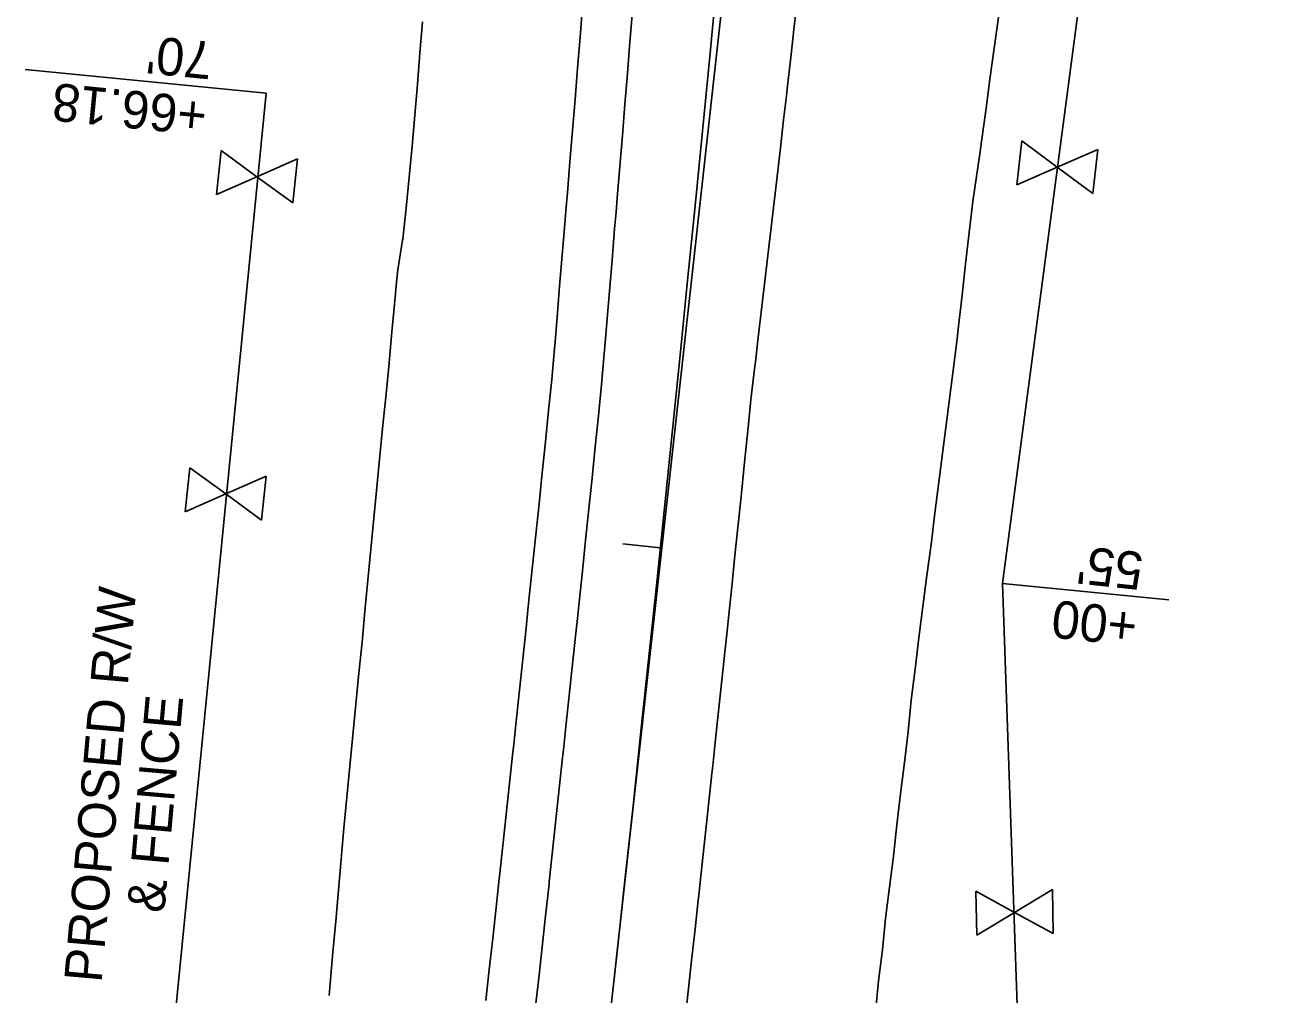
# Model space of a CAD drawing. Extents: x 634057 to 641016, y 287858 to 292331.
# Drawn here: x 634163.1 to 634363.2, y 289595.2 to 289750.2 of the extents above; entities that cross this region are included whole.
import ezdxf

# ---------------------------------------------------------------- set-up
doc = ezdxf.new("R2010")
doc.units = 0
for name, color, linetype in [('53', 7, 'Continuous'), ('R_50 Horz Alg PC PI PT', 7, 'Continuous'), ('R_50 Horz Alg Ticks', 7, 'Continuous'), ('R_Horz Alg', 7, 'Continuous'), ('R_No Plot', 7, 'Continuous'), ('R_Proposed Const Limits', 7, 'Continuous'), ('R_Proposed Road', 7, 'Continuous'), ('R_Proposed Shoulder', 7, 'Continuous'), ('R_ROW', 7, 'Continuous')]:
    doc.layers.add(name, color=color, linetype=linetype)

msp = doc.modelspace()

# ---------------------------------------------------------------- linework, layer by layer
at = {"layer": '53'}
for p, q in [((634201.66, 289739.35), (634163.14, 289743.13)), ((634345.98, 289658.38), (634319.38, 289660.99))]:
    msp.add_line(p, q, dxfattribs=at)
at = {"layer": 'R_50 Horz Alg PC PI PT'}
msp.add_lwpolyline([(634256.46, 289590.15), (634341.05, 290353.77)], dxfattribs=at)
at = {"layer": 'R_50 Horz Alg Ticks'}
msp.add_lwpolyline([(634258.7, 289667.3), (634264.67, 289666.68)], dxfattribs=at)
at = {"layer": 'R_Horz Alg'}
msp.add_arc((622866.97, 290851.82), 11459.16, 353.678846, 1.350269, dxfattribs=at)
at = {"layer": 'R_Proposed Const Limits'}
for points in [[(634318.77, 289751.89), (634318.1, 289746.91), (634317.42, 289741.94), (634316.75, 289736.96), (634316.07, 289731.98), (634315.75, 289729.64)], [(634223.48, 289715.85), (634223.5, 289716.02), (634224.04, 289720.97), (634224.54, 289725.92), (634224.99, 289730.88), (634225.44, 289735.84), (634225.89, 289740.8), (634226.26, 289745.77), (634226.65, 289750.74)], [(634315.75, 289729.64), (634314.64, 289722.04), (634314.06, 289717.05), (634313.48, 289712.06), (634312.9, 289707.08), (634312.35, 289702.09), (634312.14, 289700.13), (634311.75, 289697.1), (634311.1, 289692.12), (634310.47, 289687.15), (634310.47, 289687.14), (634309.85, 289682.16), (634309.2, 289677.18), (634308.56, 289672.2), (634307.95, 289667.22), (634307.29, 289662.24), (634306.64, 289657.27), (634306.02, 289652.28), (634305.4, 289647.3), (634304.77, 289642.32), (634304.27, 289637.33), (634303.7, 289632.34), (634303.06, 289627.37), (634302.49, 289622.38), (634301.96, 289617.39), (634301.32, 289612.41), (634300.67, 289607.43), (634300.19, 289602.44), (634299.53, 289597.46), (634299.05, 289592.46)], [(634211.74, 289595.11), (634211.92, 289597.05), (634212.35, 289602.02), (634212.79, 289606.98), (634213.24, 289611.94), (634213.66, 289616.9), (634214.12, 289621.86), (634214.57, 289626.82), (634215.04, 289631.78), (634215.53, 289636.74), (634216.02, 289641.69), (634216.51, 289646.65), (634217, 289651.61), (634217.47, 289656.56), (634217.94, 289661.52), (634218.43, 289666.48), (634218.91, 289671.43), (634219.39, 289676.39), (634219.86, 289681.35), (634220.35, 289686.3), (634220.85, 289691.26), (634221.35, 289696.21), (634221.35, 289696.22), (634221.77, 289701.18), (634222.24, 289706.13), (634222.53, 289709.15), (634222.72, 289711.09), (634223.48, 289715.85)]]:
    msp.add_lwpolyline(points, dxfattribs=at)
at = {"layer": 'R_Proposed Road'}
for points in [[(634268.6, 289590.78), (634269.15, 289595.76), (634269.69, 289600.73), (634270.24, 289605.71), (634270.74, 289610.33), (634270.78, 289610.69), (634271.32, 289615.66), (634271.86, 289620.64), (634272.4, 289625.61), (634272.93, 289630.59), (634273.06, 289631.84), (634273.46, 289635.57), (634273.99, 289640.55), (634274.52, 289645.52), (634275.05, 289650.5), (634275.35, 289653.35), (634275.57, 289655.48), (634276.09, 289660.46), (634276.61, 289665.43), (634277.12, 289670.41), (634277.59, 289674.87), (634277.64, 289675.39), (634278.15, 289680.37), (634278.66, 289685.35), (634279.17, 289690.33), (634279.76, 289695.3), (634279.89, 289696.38), (634280.34, 289700.27), (634280.93, 289705.24), (634281.51, 289710.22), (634282.09, 289715.19), (634282.4, 289717.87), (634282.67, 289720.16), (634283.24, 289725.13), (634283.82, 289730.11), (634284.39, 289735.08), (634284.88, 289739.36), (634284.96, 289740.05), (634285.52, 289745.03), (634286.09, 289750), (634286.65, 289754.98)], [(634244.74, 289593.42), (634245.29, 289598.39), (634245.84, 289603.35), (634246.38, 289608.32), (634246.89, 289612.93), (634246.92, 289613.28), (634247.46, 289618.25), (634248, 289623.21), (634248.53, 289628.18), (634249.07, 289633.15), (634249.2, 289634.39), (634249.6, 289638.11), (634250.13, 289643.08), (634250.65, 289648.05), (634251.18, 289653.01), (634251.48, 289655.86), (634251.7, 289657.98), (634252.22, 289662.95), (634252.74, 289667.92), (634253.25, 289672.88), (634253.71, 289677.33), (634253.77, 289677.85), (634254.28, 289682.82), (634254.79, 289687.79), (634255.29, 289692.76), (634255.71, 289697.74), (634255.81, 289698.82), (634256.13, 289702.71), (634256.55, 289707.69), (634256.97, 289712.67), (634257.38, 289717.65), (634257.6, 289720.33), (634257.79, 289722.63), (634258.2, 289727.61), (634258.61, 289732.58), (634259.01, 289737.56), (634259.36, 289741.85), (634259.41, 289742.54), (634259.81, 289747.52), (634260.21, 289752.5)]]:
    msp.add_lwpolyline(points, dxfattribs=at)
at = {"layer": 'R_Proposed Shoulder'}
msp.add_lwpolyline([(634236.79, 289594.3), (634237.34, 289599.26), (634237.89, 289604.22), (634238.43, 289609.19), (634238.93, 289613.8), (634238.97, 289614.15), (634239.51, 289619.11), (634240.05, 289624.07), (634240.58, 289629.04), (634241.11, 289634), (634241.25, 289635.24), (634241.64, 289638.96), (634242.17, 289643.92), (634242.7, 289648.89), (634243.22, 289653.85), (634243.52, 289656.7), (634243.74, 289658.82), (634244.26, 289663.78), (634244.78, 289668.74), (634245.29, 289673.71), (634245.75, 289678.15), (634245.81, 289678.67), (634246.32, 289683.64), (634246.83, 289688.6), (634247.33, 289693.57), (634247.75, 289698.54), (634247.85, 289699.62), (634248.17, 289703.52), (634248.59, 289708.49), (634249.01, 289713.47), (634249.42, 289718.44), (634249.64, 289721.12), (634249.83, 289723.42), (634250.24, 289728.39), (634250.64, 289733.37), (634251.05, 289738.34), (634251.39, 289742.62), (634251.45, 289743.32), (634251.85, 289748.29), (634252.25, 289753.27)], dxfattribs=at)
at = {"layer": 'R_ROW'}
for p, q in [((634321.64, 289724.69), (634322.44, 289731.72)), ((634322.44, 289731.72), (634328.12, 289727.52)), ((634193.75, 289723.13), (634194.5, 289730.16)), ((634194.5, 289730.16), (634200.21, 289725.99)), ((634328.12, 289727.52), (634334.61, 289730.34)), ((634334.61, 289730.34), (634333.81, 289723.31)), ((634200.21, 289725.99), (634206.68, 289728.85)), ((634206.68, 289728.85), (634205.92, 289721.82)), ((634328.12, 289727.52), (634321.64, 289724.69)), ((634333.81, 289723.31), (634328.12, 289727.52)), ((634200.21, 289725.99), (634193.75, 289723.13)), ((634205.92, 289721.82), (634200.21, 289725.99)), ((634188.75, 289672.41), (634189.5, 289679.45)), ((634189.5, 289679.45), (634195.21, 289675.28)), ((634195.21, 289675.28), (634201.68, 289678.14)), ((634201.68, 289678.14), (634200.92, 289671.11)), ((634195.21, 289675.28), (634188.75, 289672.41)), ((634200.92, 289671.11), (634195.21, 289675.28)), ((634315.1, 289611.81), (634321.29, 289608.41)), ((634315.25, 289604.74), (634315.1, 289611.81)), ((634321.29, 289608.41), (634327.34, 289612.08)), ((634327.34, 289612.08), (634327.49, 289605.01)), ((634321.29, 289608.41), (634315.25, 289604.74)), ((634327.49, 289605.01), (634321.29, 289608.41))]:
    msp.add_line(p, q, dxfattribs=at)
for points in [[(634329.31, 289374.55), (634319.38, 289660.99), (634353.08, 289916.2), (634363.24, 290050.68)], [(634208.8, 289235.73), (634174.82, 289467.18), (634201.66, 289739.35)]]:
    msp.add_lwpolyline(points, dxfattribs=at)

# ---------------------------------------------------------------- texts
at = {"layer": '53'}
for s, rotation, p in [("70'  ", 174.3945, (634193.33, 289747.5)), ('+66.18 ', 174.3945, (634192.45, 289738.55)), ("55'  ", 174.0637, (634342.08, 289665.88)), ('PROPOSED R/W', 84.9571, (634175.36, 289597.05)), ('+00 ', 174.0637, (634341.15, 289656.93)), ('& FENCE', 84.9571, (634185.38, 289608.2))]:
    msp.add_text(s, height=6, rotation=rotation, dxfattribs=at).set_placement(p)
at = {"layer": 'R_No Plot'}
msp.add_text('+', height=0.1, rotation=84.408, dxfattribs=at).set_placement((634271.63, 289735.15))

doc.saveas('drawing.dxf')
